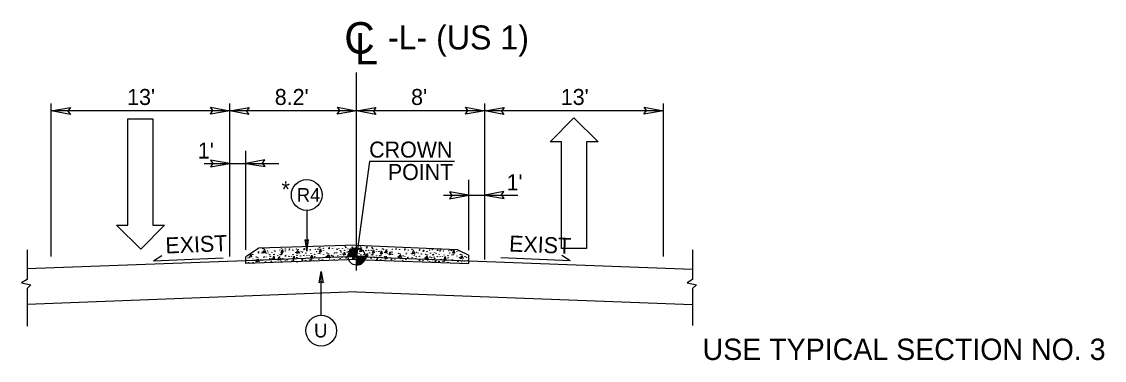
# Model space of a CAD drawing. Extents: x 573748 to 574632, y -54663 to -53209.
# Drawn here: x 574526.6 to 574628.1, y -53507.9 to -53476.1 of the extents above; entities that cross this region are included whole.
import ezdxf

# ---------------------------------------------------------------- set-up
doc = ezdxf.new("R2010")
doc.units = 0
for name, color, linetype in [('Prop Dimension', 7, 'Continuous'), ('Prop Dimension Text', 7, 'Continuous'), ('Prop Lane Arrow CELL', 7, 'Continuous'), ('Prop Terminator CELL', 7, 'Continuous'), ('Typical Arrow Superelevation CELL', 7, 'Continuous'), ('Typical Curb CELL', 7, 'Continuous'), ('Typical Grade Point Symbol CELL', 7, 'Continuous'), ('Typical ID Circle CELL', 7, 'Continuous'), ('Typical Terminator CELL', 7, 'Continuous'), ('Typical Text Centerline CELL', 7, 'Continuous'), ('Typical Text General CELL', 7, 'Continuous'), ('Typical Text ID Circle CELL', 7, 'Continuous')]:
    doc.layers.add(name, color=color, linetype=linetype)

# ---------------------------------------------------------------- blocks, each defined once
blk = doc.blocks.new('CENTERLINE TEXT CL')
at = {"layer": 'Typical Text Centerline CELL'}
blk.add_text('C', height=1.64, dxfattribs=at).set_placement((-0.546, -0.261))
blk.add_text('L', height=1.641, rotation=359.9469, dxfattribs=at).set_placement((-0.001, -0.821))

msp = doc.modelspace()

# ---------------------------------------------------------------- linework, layer by layer
at = {"layer": 'Prop Dimension'}
for p, q in [((574558.01, -53499.45), (574558.01, -53480.9)), ((574529.4, -53498.13), (574529.4, -53483.8)), ((574546.13, -53484.49), (574529.4, -53484.49)), ((574546.13, -53498.13), (574546.13, -53483.8)), ((574558.01, -53484.49), (574546.13, -53484.49)), ((574570.01, -53484.49), (574558.01, -53484.49)), ((574570.01, -53498.4), (574570.01, -53483.8)), ((574586.75, -53484.49), (574570.01, -53484.49)), ((574586.75, -53498.13), (574586.75, -53483.8)), ((574547.63, -53497.51), (574547.63, -53488.24)), ((574543.75, -53489.41), (574550.72, -53489.41)), ((574568.51, -53497.55), (574568.51, -53490.96)), ((574566.14, -53492.39), (574573.1, -53492.39)), ((574527.14, -53497.52), (574527.14, -53500.3)), ((574548.87, -53497.35), (574547.63, -53498.16)), ((574558.01, -53497.06), (574548.87, -53497.35)), ((574558.01, -53497.06), (574567.43, -53497.47)), ((574567.43, -53497.47), (574568.51, -53498.02)), ((574589.49, -53497.52), (574589.49, -53500.3)), ((574547.63, -53498.53), (574527.14, -53499.3)), ((574558.01, -53498.14), (574547.63, -53498.53)), ((574547.63, -53498.79), (574547.63, -53498.16)), ((574558.01, -53498.4), (574547.63, -53498.79)), ((574558.01, -53498.14), (574568.51, -53498.54)), ((574558.01, -53498.4), (574568.51, -53498.79)), ((574568.51, -53498.79), (574568.51, -53498.02)), ((574568.51, -53498.54), (574589.49, -53499.32)), ((574527.14, -53500.3), (574526.64, -53500.6)), ((574526.64, -53500.6), (574527.5, -53500.79)), ((574527.5, -53500.79), (574527.14, -53501.14)), ((574589.49, -53500.3), (574588.98, -53500.6)), ((574588.98, -53500.6), (574589.85, -53500.79)), ((574589.85, -53500.79), (574589.49, -53501.14)), ((574527.14, -53501.14), (574527.14, -53504.67)), ((574558.01, -53501.46), (574527.14, -53502.62)), ((574558.01, -53501.46), (574589.49, -53502.64)), ((574589.49, -53501.14), (574589.49, -53504.59))]:
    msp.add_line(p, q, dxfattribs=at)
msp.add_lwpolyline([(574567.19, -53489.23), (574559.22, -53489.23), (574558.01, -53498.14)], dxfattribs=at)
at = {"layer": 'Prop Lane Arrow CELL'}
for p, q in [((574536.59, -53495.21), (574536.59, -53485.23)), ((574536.59, -53485.23), (574538.94, -53485.23)), ((574538.94, -53485.23), (574538.94, -53495.21)), ((574576.14, -53487.4), (574578.35, -53485.16)), ((574578.35, -53485.16), (574580.63, -53487.4)), ((574577.21, -53487.4), (574576.14, -53487.4)), ((574577.21, -53497.38), (574577.21, -53487.4)), ((574580.63, -53487.4), (574579.56, -53487.4)), ((574579.56, -53487.4), (574579.56, -53497.38)), ((574537.8, -53497.45), (574535.52, -53495.21)), ((574535.52, -53495.21), (574536.59, -53495.21)), ((574540.01, -53495.21), (574537.8, -53497.45)), ((574538.94, -53495.21), (574540.01, -53495.21)), ((574579.56, -53497.38), (574577.21, -53497.38))]:
    msp.add_line(p, q, dxfattribs=at)
at = {"layer": 'Prop Terminator CELL'}
for points in [[(574531.2, -53484.82), (574529.4, -53484.49), (574531.21, -53484.19), (574530.98, -53484.51)], [(574544.34, -53484.16), (574546.13, -53484.49), (574544.32, -53484.79), (574544.55, -53484.47)], [(574547.93, -53484.82), (574546.13, -53484.49), (574547.95, -53484.19), (574547.71, -53484.51)], [(574556.22, -53484.16), (574558.01, -53484.49), (574556.2, -53484.79), (574556.43, -53484.47)], [(574559.81, -53484.82), (574558.01, -53484.49), (574559.83, -53484.19), (574559.6, -53484.51)], [(574568.22, -53484.16), (574570.01, -53484.49), (574568.2, -53484.79), (574568.43, -53484.47)], [(574571.81, -53484.82), (574570.01, -53484.49), (574571.83, -53484.19), (574571.6, -53484.51)], [(574584.95, -53484.16), (574586.75, -53484.49), (574584.93, -53484.79), (574585.17, -53484.47)], [(574544.34, -53489.74), (574546.13, -53489.41), (574544.32, -53489.11), (574544.55, -53489.43)], [(574549.43, -53489.07), (574547.63, -53489.41), (574549.45, -53489.7), (574549.21, -53489.39)], [(574566.72, -53492.72), (574568.51, -53492.39), (574566.7, -53492.09), (574566.93, -53492.41)], [(574571.81, -53492.06), (574570.01, -53492.39), (574571.83, -53492.69), (574571.6, -53492.37)]]:
    msp.add_lwpolyline(points, close=True, dxfattribs=at)
at = {"layer": 'Typical Arrow Superelevation CELL'}
for p, q in [((574539, -53498.54), (574539.78, -53498.05)), ((574539, -53498.54), (574545.52, -53498.26)), ((574578.02, -53498.54), (574571.51, -53498.26)), ((574578.02, -53498.54), (574577.25, -53498.05))]:
    msp.add_line(p, q, dxfattribs=at)
at = {"layer": 'Typical Curb CELL'}
for p, q in [((574549.26, -53497.81), (574549.34, -53497.54)), ((574549.47, -53497.71), (574549.26, -53497.81)), ((574549.34, -53497.54), (574549.47, -53497.71)), ((574550.96, -53497.78), (574551.07, -53497.49)), ((574551.11, -53497.76), (574550.96, -53497.78)), ((574551.07, -53497.49), (574551.11, -53497.76)), ((574552.42, -53497.85), (574552.49, -53497.57)), ((574552.63, -53497.74), (574552.42, -53497.85)), ((574552.49, -53497.57), (574552.63, -53497.74)), ((574554.53, -53497.72), (574554.64, -53497.42)), ((574554.69, -53497.69), (574554.53, -53497.72)), ((574554.64, -53497.42), (574554.69, -53497.69)), ((574556.79, -53498.01), (574556.89, -53497.72)), ((574556.89, -53497.72), (574556.94, -53497.99)), ((574557.33, -53497.7), (574557.44, -53497.4)), ((574557.48, -53497.67), (574557.33, -53497.7)), ((574557.44, -53497.4), (574557.48, -53497.67)), ((574558.31, -53497.7), (574558.42, -53497.4)), ((574558.47, -53497.67), (574558.31, -53497.7)), ((574558.42, -53497.4), (574558.47, -53497.67)), ((574559.5, -53497.82), (574559.61, -53497.52)), ((574559.66, -53497.79), (574559.5, -53497.82)), ((574559.61, -53497.52), (574559.66, -53497.79)), ((574560.24, -53497.9), (574560.35, -53497.61)), ((574560.35, -53497.61), (574560.4, -53497.88)), ((574560.7, -53497.78), (574560.81, -53497.49)), ((574560.86, -53497.76), (574560.7, -53497.78)), ((574560.81, -53497.49), (574560.86, -53497.76)), ((574561.06, -53497.99), (574561.17, -53497.69)), ((574561.17, -53497.69), (574561.22, -53497.96)), ((574563.23, -53497.92), (574563.31, -53497.64)), ((574563.31, -53497.64), (574563.44, -53497.82)), ((574567.02, -53497.83), (574567.13, -53497.54)), ((574567.13, -53497.54), (574567.18, -53497.81)), ((574548.01, -53498.19), (574548.12, -53497.9)), ((574548.17, -53498.17), (574548.01, -53498.19)), ((574548.12, -53497.9), (574548.17, -53498.17)), ((574548.64, -53498.62), (574548.72, -53498.34)), ((574548.85, -53498.51), (574548.64, -53498.62)), ((574548.72, -53498.34), (574548.85, -53498.51)), ((574550.17, -53498.4), (574550.27, -53498.1)), ((574550.32, -53498.37), (574550.17, -53498.4)), ((574550.27, -53498.1), (574550.32, -53498.37)), ((574550.67, -53498.48), (574550.74, -53498.21)), ((574550.88, -53498.38), (574550.67, -53498.48)), ((574550.74, -53498.21), (574550.88, -53498.38)), ((574552.05, -53498.39), (574552.15, -53498.09)), ((574552.2, -53498.36), (574552.05, -53498.39)), ((574552.15, -53498.09), (574552.2, -53498.36)), ((574553.71, -53498.3), (574553.82, -53498.01)), ((574553.87, -53498.28), (574553.71, -53498.3)), ((574553.82, -53498.01), (574553.87, -53498.28)), ((574555.26, -53498.23), (574555.34, -53497.95)), ((574555.47, -53498.12), (574555.26, -53498.23)), ((574555.34, -53497.95), (574555.47, -53498.12)), ((574556.94, -53497.99), (574556.79, -53498.01)), ((574557.64, -53498.39), (574557.71, -53498.11)), ((574557.85, -53498.28), (574557.64, -53498.39)), ((574557.71, -53498.11), (574557.85, -53498.28)), ((574558.89, -53498.13), (574559, -53497.84)), ((574559.05, -53498.11), (574558.89, -53498.13)), ((574559, -53497.84), (574559.05, -53498.11)), ((574560.4, -53497.88), (574560.24, -53497.9)), ((574560.69, -53498.39), (574560.79, -53498.09)), ((574560.84, -53498.36), (574560.69, -53498.39)), ((574560.79, -53498.09), (574560.84, -53498.36)), ((574561.22, -53497.96), (574561.06, -53497.99)), ((574561.98, -53498.25), (574562.06, -53497.98)), ((574562.19, -53498.15), (574561.98, -53498.25)), ((574562.06, -53497.98), (574562.19, -53498.15)), ((574563.44, -53497.82), (574563.23, -53497.92)), ((574564.49, -53498.37), (574564.57, -53498.09)), ((574564.7, -53498.26), (574564.49, -53498.37)), ((574564.57, -53498.09), (574564.7, -53498.26)), ((574566.2, -53498.42), (574566.31, -53498.13)), ((574566.36, -53498.4), (574566.2, -53498.42)), ((574566.31, -53498.13), (574566.36, -53498.4)), ((574567.18, -53497.81), (574567.02, -53497.83)), ((574567.75, -53498.34), (574567.83, -53498.07)), ((574567.96, -53498.24), (574567.75, -53498.34)), ((574567.83, -53498.07), (574567.96, -53498.24))]:
    msp.add_line(p, q, dxfattribs=at)
for centre in [(574548.3, -53497.75), (574548.81, -53497.79), (574548.83, -53497.7), (574549.14, -53497.8), (574549.18, -53497.72), (574549.24, -53497.39), (574549.38, -53497.45), (574549.49, -53497.78), (574549.66, -53497.63), (574549.73, -53497.8), (574550.07, -53497.78), (574550.32, -53497.58), (574550.39, -53497.68), (574550.82, -53497.52), (574550.98, -53497.36), (574551.34, -53497.43), (574551.34, -53497.63), (574551.69, -53497.53), (574551.72, -53497.44), (574552.03, -53497.54), (574552.33, -53497.76), (574552.39, -53497.42), (574552.54, -53497.48), (574552.65, -53497.81), (574552.82, -53497.67), (574552.96, -53497.73), (574553.09, -53497.49), (574553.12, -53497.4), (574553.33, -53497.5), (574553.36, -53497.42), (574553.67, -53497.51), (574554.17, -53497.46), (574554.25, -53497.69), (574554.4, -53497.45), (574554.55, -53497.3), (574554.6, -53497.81), (574554.91, -53497.56), (574554.92, -53497.36), (574555.24, -53497.8), (574555.43, -53497.4), (574555.45, -53497.32), (574555.76, -53497.41), (574555.97, -53497.77), (574556.17, -53497.45), (574556.16, -53497.79), (574556.35, -53497.41), (574556.49, -53497.58), (574556.55, -53497.72), (574556.69, -53497.39), (574556.89, -53497.56), (574556.94, -53497.19), (574557.01, -53497.29), (574557.14, -53497.71), (574557.19, -53497.43), (574557.29, -53497.64), (574557.59, -53497.34), (574557.62, -53497.25), (574557.71, -53497.58), (574557.76, -53497.8), (574558.01, -53497.44), (574558.21, -53497.46), (574558.39, -53497.23), (574558.46, -53497.33), (574558.62, -53497.6), (574558.9, -53497.6), (574558.96, -53497.34), (574558.99, -53497.25), (574559.14, -53497.56), (574559.22, -53497.79), (574559.37, -53497.55), (574559.45, -53497.3), (574559.52, -53497.4), (574559.88, -53497.66), (574559.89, -53497.46), (574560.11, -53497.64), (574560.44, -53497.36), (574560.51, -53497.46), (574560.62, -53497.74), (574561.33, -53497.72), (574561.35, -53497.47), (574561.69, -53497.47), (574561.72, -53497.39), (574562.03, -53497.48), (574562.52, -53497.51), (574562.54, -53497.43), (574562.69, -53497.8), (574562.85, -53497.52), (574563.2, -53497.5), (574563.35, -53497.56), (574563.63, -53497.74), (574563.78, -53497.8), (574563.91, -53497.56), (574563.94, -53497.47), (574564.26, -53497.66), (574564.29, -53497.57), (574564.6, -53497.67), (574564.85, -53497.52), (574564.94, -53497.82), (574565.11, -53497.5), (574565.31, -53497.78), (574565.59, -53497.6), (574565.61, -53497.52), (574565.82, -53497.62), (574565.85, -53497.53), (574566.16, -53497.63), (574566.66, -53497.58), (574566.74, -53497.8), (574566.89, -53497.57), (574567.4, -53497.68), (574567.57, -53497.6), (574547.82, -53498.27), (574547.89, -53498.69), (574547.92, -53498.27), (574547.98, -53498.2), (574548.29, -53497.95), (574548.29, -53498.36), (574548.33, -53498.7), (574548.56, -53498.52), (574548.62, -53498.19), (574548.76, -53498.25), (574548.87, -53498.58), (574549.05, -53498.43), (574549.19, -53498.49), (574549.32, -53498.25), (574549.35, -53498.16), (574549.48, -53498.59), (574549.54, -53497.84), (574549.54, -53498.18), (574549.63, -53498.46), (574549.79, -53498.68), (574549.87, -53497.97), (574549.88, -53498.35), (574549.93, -53498.11), (574550.02, -53498.59), (574550.07, -53498.3), (574550.27, -53497.95), (574550.41, -53498.65), (574550.58, -53498.39), (574550.64, -53498.06), (574550.79, -53498.12), (574550.87, -53497.95), (574550.9, -53498.45), (574550.96, -53498.62), (574550.97, -53497.95), (574551.03, -53497.87), (574551.07, -53498.3), (574551.22, -53498.36), (574551.35, -53498.12), (574551.35, -53498.52), (574551.37, -53498.03), (574551.51, -53498.46), (574551.68, -53498.13), (574551.76, -53498.36), (574551.91, -53498.12), (574551.96, -53498.55), (574552.05, -53498.55), (574552.06, -53497.96), (574552.12, -53498.47), (574552.42, -53498.23), (574552.43, -53498.03), (574552.43, -53498.64), (574552.78, -53498.09), (574552.9, -53498.48), (574552.93, -53498.39), (574553.08, -53498.04), (574553.24, -53498.49), (574553.26, -53497.82), (574553.35, -53498.05), (574553.43, -53498.27), (574553.57, -53498.03), (574553.62, -53498.47), (574553.72, -53498.47), (574553.73, -53497.88), (574553.78, -53498.39), (574554.09, -53497.94), (574554.09, -53498.15), (574554.09, -53498.56), (574554.44, -53497.88), (574554.48, -53498.39), (574554.51, -53498.3), (574554.54, -53497.88), (574554.82, -53498.4), (574554.91, -53497.97), (574555.18, -53498.13), (574555.38, -53497.86), (574555.49, -53498.19), (574555.63, -53498.46), (574555.67, -53498.04), (574555.81, -53498.1), (574555.92, -53498.42), (574555.94, -53497.86), (574556.1, -53498.2), (574556.25, -53498.07), (574556.47, -53498.32), (574556.5, -53497.96), (574556.64, -53498.2), (574556.69, -53497.91), (574557.03, -53498.26), (574557.18, -53498.1), (574557.38, -53498.04), (574557.51, -53498.14), (574557.98, -53497.83), (574558.07, -53498.24), (574558.08, -53498.09), (574558.25, -53497.84), (574558.3, -53498.21), (574558.37, -53498.29), (574558.41, -53497.98), (574558.64, -53498.23), (574558.7, -53497.93), (574558.82, -53498.17), (574558.89, -53498.32), (574559.3, -53498.21), (574559.37, -53498.29), (574559.41, -53497.98), (574559.51, -53497.98), (574559.57, -53497.91), (574559.64, -53498.18), (574559.88, -53498.07), (574559.92, -53498.44), (574559.95, -53498.35), (574560.15, -53498.07), (574560.25, -53498.07), (574560.26, -53498.45), (574560.31, -53497.99), (574560.38, -53498.27), (574560.62, -53498.15), (574560.88, -53497.88), (574560.9, -53498.26), (574561.26, -53498.43), (574561.28, -53498.34), (574561.36, -53497.92), (574561.59, -53498.44), (574561.9, -53498.16), (574561.95, -53497.83), (574562.1, -53497.89), (574562.21, -53498.22), (574562.35, -53498.49), (574562.38, -53498.07), (574562.53, -53498.13), (574562.64, -53498.44), (574562.66, -53497.89), (574562.82, -53498.23), (574563.15, -53497.83), (574563.19, -53498.33), (574563.21, -53498.24), (574563.46, -53497.89), (574563.52, -53498.33), (574563.6, -53498.16), (574563.89, -53498.11), (574563.9, -53498.51), (574563.93, -53498.42), (574564.07, -53497.9), (574564.23, -53498.52), (574564.41, -53498.28), (574564.46, -53497.94), (574564.61, -53498), (574564.72, -53498.33), (574564.86, -53498.61), (574564.89, -53498.19), (574565.04, -53498.24), (574565.15, -53498.56), (574565.17, -53498), (574565.2, -53497.92), (574565.28, -53498.2), (574565.33, -53498.34), (574565.39, -53498.6), (574565.42, -53498.51), (574565.46, -53497.84), (574565.57, -53498.16), (574565.73, -53498.6), (574565.75, -53497.94), (574565.84, -53498.16), (574565.92, -53498.39), (574566.06, -53498.15), (574566.11, -53498.58), (574566.21, -53498.58), (574566.22, -53498), (574566.27, -53498.51), (574566.58, -53498.06), (574566.58, -53498.26), (574566.58, -53498.67), (574566.93, -53498), (574566.97, -53498.5), (574567, -53498.42), (574567.03, -53498), (574567.09, -53497.92), (574567.31, -53498.51), (574567.4, -53498.09), (574567.5, -53498.63), (574567.53, -53498.55), (574567.67, -53498.25), (574567.73, -53497.92), (574567.84, -53498.64), (574567.87, -53497.98), (574567.99, -53498.31), (574568.12, -53498.58), (574568.16, -53498.16), (574568.3, -53498.22), (574568.41, -53498.53)]:
    msp.add_ellipse(centre, major_axis=(0.0001, 0.0192), ratio=0.533333, dxfattribs=at)
for centre in [(574552.6, -53497.99), (574555.45, -53498.37), (574562.16, -53498.4), (574563.41, -53498.07), (574564.67, -53498.51), (574567.94, -53498.49)]:
    msp.add_ellipse(centre, major_axis=(-0.0001, -0.0219), ratio=0.533333, start_param=2.050606, end_param=4.270718, dxfattribs=at)
at = {"layer": 'Typical Grade Point Symbol CELL'}
for p, q in [((574558.01, -53498.14), (574558.01, -53497.34)), ((574557.21, -53498.14), (574558.01, -53498.14)), ((574558.02, -53498.95), (574558.01, -53498.14)), ((574558.82, -53498.14), (574558.01, -53498.14)), ((574558.01, -53498.14), (574558.02, -53498.95))]:
    msp.add_line(p, q, dxfattribs=at)
for points in [[(574557.3, -53497.77), (574557.3, -53498.14)], [(574557.31, -53497.75), (574557.31, -53498.14)], [(574557.33, -53497.72), (574557.33, -53498.14)], [(574557.35, -53497.69), (574557.35, -53498.14)], [(574557.36, -53497.67), (574557.36, -53498.14)], [(574557.38, -53497.65), (574557.38, -53498.14)], [(574557.4, -53497.63), (574557.4, -53498.14)], [(574557.41, -53497.61), (574557.41, -53498.14)], [(574557.43, -53497.59), (574557.43, -53498.14)], [(574557.44, -53497.58), (574557.44, -53498.14)], [(574557.46, -53497.56), (574557.46, -53498.14)], [(574557.48, -53497.55), (574557.48, -53498.14)], [(574557.49, -53497.53), (574557.49, -53498.14)], [(574557.51, -53497.52), (574557.51, -53498.14)], [(574557.52, -53497.5), (574557.52, -53498.14)], [(574557.54, -53497.49), (574557.54, -53498.14)], [(574557.56, -53497.48), (574557.56, -53498.14)], [(574557.57, -53497.47), (574557.57, -53498.14)], [(574557.59, -53497.46), (574557.59, -53498.14)], [(574557.6, -53497.45), (574557.6, -53498.14)], [(574557.62, -53497.44), (574557.62, -53498.14)], [(574557.64, -53497.43), (574557.64, -53498.14)], [(574557.65, -53497.42), (574557.65, -53498.14)], [(574557.67, -53497.42), (574557.67, -53498.14)], [(574557.69, -53497.41), (574557.69, -53498.14)], [(574557.7, -53497.4), (574557.7, -53498.14)], [(574557.72, -53497.4), (574557.72, -53498.14)], [(574557.73, -53497.39), (574557.73, -53498.14)], [(574557.75, -53497.38), (574557.75, -53498.14)], [(574557.77, -53497.38), (574557.77, -53498.14)], [(574557.78, -53497.37), (574557.78, -53498.14)], [(574557.8, -53497.37), (574557.8, -53498.14)], [(574557.81, -53497.36), (574557.81, -53498.14)], [(574557.83, -53497.36), (574557.83, -53498.14)], [(574557.85, -53497.36), (574557.85, -53498.14)], [(574557.86, -53497.35), (574557.86, -53498.14)], [(574557.88, -53497.35), (574557.88, -53498.14)], [(574557.89, -53497.35), (574557.89, -53498.14)], [(574557.91, -53497.34), (574557.91, -53498.14)], [(574557.93, -53497.34), (574557.93, -53498.14)], [(574557.94, -53497.34), (574557.94, -53498.14)], [(574557.96, -53497.34), (574557.96, -53498.14)], [(574557.98, -53497.34), (574557.98, -53498.14)], [(574557.99, -53497.34), (574557.99, -53498.14)], [(574558.01, -53497.34), (574558.01, -53497.34), (574558.01, -53498.14)], [(574557.22, -53498.03), (574557.22, -53498.14)], [(574557.23, -53497.95), (574557.23, -53498.14)], [(574557.25, -53497.89), (574557.25, -53498.14)], [(574557.27, -53497.85), (574557.27, -53498.14)], [(574557.28, -53497.81), (574557.28, -53498.14)], [(574558.03, -53498.14), (574558.03, -53498.95), (574558.03, -53498.95)], [(574558.04, -53498.14), (574558.04, -53498.95)], [(574558.06, -53498.14), (574558.06, -53498.95)], [(574558.08, -53498.14), (574558.08, -53498.95)], [(574558.09, -53498.14), (574558.09, -53498.95)], [(574558.11, -53498.14), (574558.11, -53498.94)], [(574558.12, -53498.14), (574558.12, -53498.94)], [(574558.14, -53498.14), (574558.14, -53498.94)], [(574558.16, -53498.14), (574558.16, -53498.94)], [(574558.17, -53498.14), (574558.17, -53498.93)], [(574558.19, -53498.14), (574558.19, -53498.93)], [(574558.2, -53498.14), (574558.2, -53498.93)], [(574558.22, -53498.14), (574558.22, -53498.92)], [(574558.24, -53498.14), (574558.24, -53498.92)], [(574558.25, -53498.14), (574558.25, -53498.91)], [(574558.27, -53498.14), (574558.27, -53498.91)], [(574558.29, -53498.14), (574558.29, -53498.9)], [(574558.3, -53498.14), (574558.3, -53498.9)], [(574558.32, -53498.14), (574558.32, -53498.89)], [(574558.33, -53498.14), (574558.33, -53498.88)], [(574558.35, -53498.14), (574558.35, -53498.88)], [(574558.37, -53498.14), (574558.37, -53498.87)], [(574558.38, -53498.14), (574558.38, -53498.86)], [(574558.4, -53498.14), (574558.4, -53498.85)], [(574558.41, -53498.14), (574558.41, -53498.84)], [(574558.43, -53498.14), (574558.43, -53498.83)], [(574558.45, -53498.14), (574558.45, -53498.82)], [(574558.46, -53498.14), (574558.46, -53498.81)], [(574558.48, -53498.14), (574558.48, -53498.8)], [(574558.49, -53498.14), (574558.49, -53498.79)], [(574558.51, -53498.14), (574558.51, -53498.78)], [(574558.53, -53498.14), (574558.53, -53498.77)], [(574558.54, -53498.14), (574558.54, -53498.75)], [(574558.56, -53498.14), (574558.56, -53498.74)], [(574558.58, -53498.14), (574558.58, -53498.72)], [(574558.59, -53498.14), (574558.59, -53498.71)], [(574558.61, -53498.14), (574558.61, -53498.69)], [(574558.62, -53498.14), (574558.62, -53498.67)], [(574558.64, -53498.14), (574558.64, -53498.65)], [(574558.66, -53498.14), (574558.66, -53498.63)], [(574558.67, -53498.14), (574558.67, -53498.61)], [(574558.69, -53498.14), (574558.69, -53498.59)], [(574558.7, -53498.14), (574558.7, -53498.56)], [(574558.72, -53498.14), (574558.72, -53498.53)], [(574558.74, -53498.14), (574558.74, -53498.5)], [(574558.75, -53498.14), (574558.75, -53498.47)], [(574558.77, -53498.14), (574558.77, -53498.43)], [(574558.78, -53498.14), (574558.78, -53498.38)], [(574558.8, -53498.14), (574558.8, -53498.33)], [(574558.82, -53498.14), (574558.82, -53498.23)]]:
    msp.add_lwpolyline(points, dxfattribs=at)
msp.add_circle((574558.02, -53498.14), 0.806, dxfattribs=at)
for start, end in [(90.0095, 180.0095), (270.0095, 0.0095)]:
    msp.add_arc((574558.02, -53498.14), 0.806, start, end, dxfattribs=at)
at = {"layer": 'Typical ID Circle CELL'}
for p, q in [((574553.34, -53493.81), (574553.34, -53497.64)), ((574554.7, -53503.63), (574554.7, -53499.55))]:
    msp.add_line(p, q, dxfattribs=at)
for centre in [(574553.34, -53492.37), (574554.7, -53505.08)]:
    msp.add_circle(centre, 1.44, dxfattribs=at)
at = {"layer": 'Typical Terminator CELL'}
for points in [[(574553.15, -53496.58), (574553.34, -53497.64), (574553.52, -53496.58), (574553.34, -53496.71)], [(574554.52, -53500.61), (574554.7, -53499.55), (574554.88, -53500.61), (574554.7, -53500.48)]]:
    msp.add_lwpolyline(points, close=True, dxfattribs=at)

# ---------------------------------------------------------------- block references
at = {"layer": 'Prop Dimension', "xscale": 1.8000000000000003, "yscale": 1.8000000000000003}
msp.add_blockref('CENTERLINE TEXT CL', (574557.84, -53478.66), dxfattribs=at)

# ---------------------------------------------------------------- texts
at = {"layer": 'Prop Dimension Text'}
for s, height, p in [('-L- (US 1)', 2.25, (574560.95, -53478.74)), ("13'", 1.5, (574536.52, -53483.94)), ("8.2'", 1.5, (574550.35, -53483.94)), ("8'", 1.5, (574563.12, -53483.94)), ("13'", 1.5, (574577.14, -53483.94)), ("1'", 1.5, (574543.14, -53488.96)), ('CROWN', 1.5, (574559.19, -53488.87)), ('POINT', 1.5, (574560.94, -53490.97)), ("1'", 1.5, (574572.06, -53491.94)), ('*', 1.5, (574550.99, -53492.59))]:
    msp.add_text(s, height=height, dxfattribs=at).set_placement(p)
for rotation, p in [(2.4521, (574540.14, -53497.86)), (357.5479, (574572.28, -53497.66))]:
    msp.add_text('EXIST', height=1.5, rotation=rotation, dxfattribs=at).set_placement(p)
at = {"layer": 'Typical Text General CELL'}
msp.add_text('USE TYPICAL SECTION NO. 3', height=2, dxfattribs=at).set_placement((574590.42, -53507.83))
at = {"layer": 'Typical Text ID Circle CELL'}
for s, height, p in [('R4', 1.291, (574552.41, -53493.01)), ('U', 1.29, (574554.03, -53505.72))]:
    msp.add_text(s, height=height, dxfattribs=at).set_placement(p)

doc.saveas('drawing.dxf')
